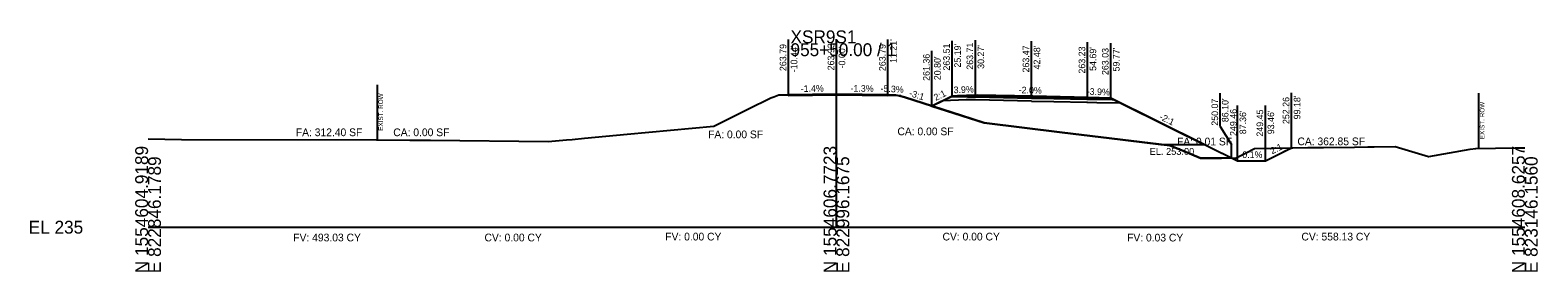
# Model space of a CAD drawing. Extents: x -26 to 823017, y -16 to 1558356.
# Drawn here: x -25.7 to 302.8, y 3490.3 to 3542.8 of the extents above; entities that cross this region are included whole.
import ezdxf

# ---------------------------------------------------------------- set-up
doc = ezdxf.new("R2010")
doc.units = 0
for name, color, linetype in [('ASPHALT_19MM1', 7, 'Continuous'), ('CONST_DCH', 7, 'Continuous'), ('CONST_LV3', 7, 'Continuous'), ('Draft_XS_Grid', 7, 'Continuous'), ('DTM_CORRIDOR', 7, 'Continuous'), ('DTM_P_FINISHED_GRADE2', 7, 'Continuous'), ('DTM_TEMP_DROP', 7, 'Continuous'), ('DTM_X_GROUND', 7, 'Continuous'), ('PROFILES_DCH_2', 7, 'Continuous'), ('XS_CELL', 7, 'Continuous'), ('XS_P_ASPHALT', 7, 'Continuous'), ('XS_P_DR_GRAVEL', 7, 'Continuous'), ('XS_P_GROUND', 7, 'Continuous'), ('XS_P_NULL_POINT', 7, 'Continuous'), ('XS_P_SHOULDER', 7, 'Continuous'), ('XS_P_SUBGRADE_GRANULAR', 7, 'Continuous'), ('XS_P_SUBGRADE_LEVELING', 7, 'Continuous'), ('XS_P_SUBGRADE_MILLING', 7, 'Continuous'), ('XS_P_SUBGRADE_UNDERCUT', 7, 'Continuous'), ('XS_P_TX_CLEARZONE', 7, 'Continuous'), ('XS_P_TX_FS_BS', 7, 'Continuous'), ('XS_SHEET_EW_TX_AREA', 7, 'Continuous'), ('XS_SHEET_EW_TX_VOLUME', 7, 'Continuous'), ('XS_X_ROW', 7, 'Continuous')]:
    doc.layers.add(name, color=color, linetype=linetype)

msp = doc.modelspace()

# ---------------------------------------------------------------- linework, layer by layer
at = {"layer": 'ASPHALT_19MM1'}
msp.add_lwpolyline([(180.27, 3528.34), (192.48, 3528.1), (197.4, 3528), (204.55, 3527.86), (204.69, 3527.86), (204.69, 3528.06), (204.55, 3528.07), (197.4, 3528.21), (192.48, 3528.31), (180.27, 3528.55), (180.27, 3528.34)], dxfattribs=at)
at = {"layer": 'CONST_DCH'}
msp.add_lwpolyline([(180.27, 3528.55), (192.48, 3528.31), (197.4, 3528.21), (204.55, 3528.07), (204.69, 3528.06), (204.69, 3528.23), (204.55, 3528.23), (197.4, 3528.37), (192.48, 3528.47), (180.27, 3528.71), (180.27, 3528.55)], dxfattribs=at)
at = {"layer": 'CONST_LV3'}
for points in [[(0, 3519.21), (7.25, 3519.1), (49.77, 3518.97), (57.04, 3518.94), (61.52, 3518.93), (87.16, 3518.66), (91.17, 3518.98), (92.43, 3519.1), (95.09, 3519.35), (104.41, 3520.21), (123.29, 3521.97), (130.66, 3525.65), (135.69, 3528.14), (136.35, 3528.38), (137.42, 3528.76), (139.56, 3528.79), (139.56, 3528.79)], [(150, 3528.93), (164, 3528.65)], [(161.21, 3528.79), (161.21, 3528.79), (162.9, 3528.77), (163.77, 3528.54), (164.84, 3528.27), (170.5, 3526.46), (170.8, 3526.36), (171, 3526.46), (175.19, 3528.51), (178.63, 3528.65), (180.27, 3528.71), (188.61, 3528.55), (192.48, 3528.47), (197.4, 3528.37), (200.08, 3528.32), (204.55, 3528.23), (204.69, 3528.23), (204.7, 3528.23), (209.77, 3528.03), (230.38, 3517.89), (237.36, 3514.46), (241.3, 3514.45), (243.46, 3514.45), (246.87, 3516.12), (247.8, 3516.58), (249.07, 3517.21), (249.18, 3517.26), (249.48, 3517.26), (252.74, 3517.32), (262.88, 3517.43), (265.76, 3517.47), (266.2, 3517.47), (266.78, 3517.48), (267.16, 3517.48), (271.74, 3517.52), (279.04, 3515.41), (279.1, 3515.39), (288.11, 3516.94), (289.31, 3517.13), (297.91, 3517.26), (300, 3517.29)], [(163.36, 3528.67), (164, 3528.65), (164, 3528.65)], [(170.8, 3526.36), (171, 3526.46), (175.19, 3528.51), (176.41, 3528.56), (180.27, 3528.71)], [(209.77, 3528.03), (224.38, 3520.84), (236.1, 3515.07)]]:
    msp.add_lwpolyline(points, dxfattribs=at)
at = {"layer": 'DTM_P_FINISHED_GRADE2'}
msp.add_lwpolyline([(139.56, 3528.79), (150, 3528.93), (161.21, 3528.79)], dxfattribs=at)
at = {"layer": 'DTM_X_GROUND'}
for points in [[(0, 3519.21), (7.25, 3519.1), (49.77, 3518.97), (57.04, 3518.94), (61.52, 3518.93), (87.16, 3518.66), (91.17, 3518.98), (92.43, 3519.1), (95.09, 3519.35), (104.41, 3520.21), (123.29, 3521.97), (130.66, 3525.65), (135.69, 3528.14), (136.35, 3528.38), (137.42, 3528.76), (146.92, 3528.89), (150.25, 3528.93), (153.12, 3528.89), (162.9, 3528.77), (163.77, 3528.54), (164.84, 3528.27), (177.24, 3524.29), (182.18, 3522.7), (199.2, 3520.63), (222.63, 3517.76), (225.55, 3516.58), (229.34, 3515.02), (233.93, 3515.05), (237.08, 3515.08), (239.28, 3516.15), (241.1, 3517.13), (249.48, 3517.28), (262.88, 3517.43), (266.78, 3517.48), (271.74, 3517.52), (279.04, 3515.41), (279.1, 3515.39), (288.11, 3516.94), (289.31, 3517.13), (297.91, 3517.26), (300, 3517.29)], [(0, 3519.21), (7.25, 3519.1), (49.77, 3518.97), (57.04, 3518.94), (61.52, 3518.93), (87.16, 3518.66), (91.17, 3518.98), (92.43, 3519.1), (95.09, 3519.35), (104.41, 3520.21), (123.29, 3521.97), (130.66, 3525.65), (135.69, 3528.14), (136.35, 3528.38), (137.42, 3528.76), (146.92, 3528.89), (150.25, 3528.93), (153.12, 3528.89), (162.9, 3528.77), (163.77, 3528.54), (164.84, 3528.27), (170.5, 3526.46), (170.8, 3526.36), (171, 3526.46), (175.19, 3528.51), (178.63, 3528.65), (180.27, 3528.71), (188.61, 3528.55), (192.48, 3528.47), (197.4, 3528.37), (200.08, 3528.32), (204.55, 3528.23), (204.69, 3528.23), (204.7, 3528.23), (209.77, 3528.03), (230.38, 3517.89), (237.36, 3514.46), (241.3, 3514.45), (243.46, 3514.45), (246.87, 3516.12), (247.8, 3516.58), (249.07, 3517.21), (249.18, 3517.26), (249.48, 3517.26), (252.74, 3517.32), (262.88, 3517.43), (265.76, 3517.47), (266.2, 3517.47), (266.78, 3517.48), (267.16, 3517.48), (271.74, 3517.52), (279.04, 3515.41), (279.1, 3515.39), (288.11, 3516.94), (289.31, 3517.13), (297.91, 3517.26), (300, 3517.29)], [(0, 3519.21), (7.25, 3519.1), (49.77, 3518.97), (57.04, 3518.94), (61.52, 3518.93), (87.16, 3518.66), (91.17, 3518.98), (92.43, 3519.1), (95.09, 3519.35), (104.41, 3520.21), (123.29, 3521.97), (130.66, 3525.65), (135.69, 3528.14), (136.35, 3528.38), (137.42, 3528.76), (139.56, 3528.79), (139.56, 3528.79), (150, 3528.93), (150, 3528.93), (150, 3528.93), (150, 3528.93), (150, 3528.93), (150, 3528.93), (150, 3528.93), (150, 3528.93), (161.21, 3528.79), (161.21, 3528.79), (161.21, 3528.79), (162.9, 3528.77), (163.77, 3528.54), (164.84, 3528.27), (170.5, 3526.46), (170.8, 3526.36), (171, 3526.46), (175.19, 3528.51), (178.63, 3528.65), (180.27, 3528.71), (188.61, 3528.55), (192.48, 3528.47), (197.4, 3528.37), (200.08, 3528.32), (204.55, 3528.23), (204.69, 3528.23), (204.7, 3528.23), (209.77, 3528.03), (230.38, 3517.89), (237.36, 3514.46), (241.3, 3514.45), (243.46, 3514.45), (246.87, 3516.12), (247.8, 3516.58), (249.07, 3517.21), (249.18, 3517.26), (249.48, 3517.26), (252.74, 3517.32), (262.88, 3517.43), (265.76, 3517.47), (266.2, 3517.47), (266.78, 3517.48), (267.16, 3517.48), (271.74, 3517.52), (279.04, 3515.41), (279.1, 3515.39), (288.11, 3516.94), (289.31, 3517.13), (297.91, 3517.26), (300, 3517.29)]]:
    msp.add_lwpolyline(points, dxfattribs=at)
at = {"layer": 'XS_CELL'}
for p, q in [((150, 3500), (150, 3540)), ((0, 3500), (150, 3500)), ((150, 3500), (300, 3500))]:
    msp.add_line(p, q, dxfattribs=at)
at = {"layer": 'XS_P_ASPHALT'}
msp.add_lwpolyline([(139.56, 3528.66), (150, 3528.8), (150, 3528.8), (161.21, 3528.66), (161.21, 3528.66), (161.21, 3528.79), (161.21, 3528.79), (150, 3528.93), (150, 3528.93), (139.56, 3528.79), (139.56, 3528.66)], dxfattribs=at)
at = {"layer": 'XS_P_DR_GRAVEL'}
for points in [[(176.41, 3528.56), (175.19, 3528.51), (175.07, 3528.46), (175.04, 3528.44), (178.59, 3528.37), (180.27, 3528.34), (180.27, 3528.48), (180.27, 3528.71), (176.41, 3528.56)], [(209.53, 3528.04), (204.69, 3528.23), (204.69, 3527.86), (204.69, 3527.86), (210.05, 3527.75), (210.36, 3527.74), (210.32, 3527.76), (209.77, 3528.03), (209.53, 3528.04)]]:
    msp.add_lwpolyline(points, dxfattribs=at)
at = {"layer": 'XS_P_GROUND'}
for points in [[(163.76, 3528.54), (163.36, 3528.67), (163.36, 3528.67)], [(236.1, 3515.07), (233.93, 3515.05), (233.93, 3515.05), (229.34, 3515.02), (229.34, 3515.02), (229.34, 3515.02), (225.55, 3516.58), (225.55, 3516.58), (222.63, 3517.76), (222.63, 3517.76), (199.2, 3520.63), (199.2, 3520.63), (182.18, 3522.7), (177.24, 3524.29), (177.24, 3524.29), (164.84, 3528.27), (164.84, 3528.27), (164.84, 3528.27), (163.77, 3528.54), (163.77, 3528.54), (163.77, 3528.54), (163.76, 3528.54)], [(163.76, 3528.54), (163.77, 3528.54), (163.77, 3528.54), (163.77, 3528.54), (164.84, 3528.27), (164.84, 3528.27), (164.84, 3528.27), (177.24, 3524.29), (177.24, 3524.29), (182.18, 3522.7), (199.2, 3520.63), (199.2, 3520.63), (222.63, 3517.76), (222.63, 3517.76), (225.55, 3516.58), (225.55, 3516.58), (229.34, 3515.02), (229.34, 3515.02), (229.34, 3515.02), (233.93, 3515.05), (233.93, 3515.05), (236.1, 3515.07)], [(175.19, 3528.51), (170.8, 3526.36)], [(209.77, 3528.03), (237.36, 3514.46), (243.46, 3514.45), (249.18, 3517.26)]]:
    msp.add_lwpolyline(points, dxfattribs=at)
at = {"layer": 'XS_P_SHOULDER'}
for points in [[(175.19, 3528.51), (176.41, 3528.56), (180.27, 3528.71)], [(209.77, 3528.03), (209.53, 3528.04), (204.69, 3528.23)]]:
    msp.add_lwpolyline(points, dxfattribs=at)
at = {"layer": 'XS_P_SUBGRADE_GRANULAR'}
for points in [[(180.27, 3527.67), (178.24, 3527.71), (173.15, 3527.51)], [(192.48, 3527.43), (180.27, 3527.67)], [(192.48, 3527.43), (197.4, 3527.33), (204.55, 3527.19), (204.69, 3527.19)], [(204.69, 3527.19), (206.72, 3527.15), (211.77, 3527.05)]]:
    msp.add_lwpolyline(points, dxfattribs=at)
at = {"layer": 'XS_P_SUBGRADE_LEVELING'}
msp.add_lwpolyline([(139.56, 3528.66), (146.92, 3528.76), (146.92, 3528.76), (150, 3528.8), (150.25, 3528.8), (150.25, 3528.8), (153.12, 3528.77), (153.12, 3528.77), (161.21, 3528.66), (161.21, 3528.66)], dxfattribs=at)
msp.add_lwpolyline([(139.56, 3528.66), (146.92, 3528.76), (146.92, 3528.76), (150, 3528.8), (150.25, 3528.8), (150.25, 3528.8), (153.12, 3528.77), (153.12, 3528.77), (161.21, 3528.66), (161.21, 3528.66)], dxfattribs=at)
at = {"layer": 'XS_P_SUBGRADE_MILLING'}
msp.add_lwpolyline([(161.21, 3528.79), (161.21, 3528.79), (161.21, 3528.66), (161.21, 3528.66), (153.12, 3528.77), (153.12, 3528.77), (150.25, 3528.8), (150.25, 3528.8), (150, 3528.8), (146.92, 3528.76), (146.92, 3528.76), (139.56, 3528.66), (139.56, 3528.79), (146.92, 3528.89), (146.92, 3528.89), (150, 3528.93), (150.25, 3528.93), (150.25, 3528.93), (153.12, 3528.89), (153.12, 3528.89), (161.21, 3528.79)], dxfattribs=at)
at = {"layer": 'XS_P_SUBGRADE_UNDERCUT'}
msp.add_lwpolyline([(170.8, 3526.36), (182.18, 3522.7), (220.68, 3518), (230.16, 3518), (209.77, 3528.03), (204.77, 3528.23), (192.77, 3528.47), (180.77, 3528.71), (175.19, 3528.51)], close=True, dxfattribs=at)
at = {"layer": 'XS_P_TX_CLEARZONE'}
for p, q in [((139.56, 3528.79), (139.56, 3540.79)), ((150, 3528.93), (150, 3540.93)), ((161.21, 3528.79), (161.21, 3540.79)), ((170.8, 3526.36), (170.8, 3538.36)), ((175.19, 3528.51), (175.19, 3540.51)), ((180.27, 3528.71), (180.27, 3540.71)), ((192.48, 3528.47), (192.48, 3540.47)), ((204.69, 3528.23), (204.69, 3540.23)), ((209.77, 3528.03), (209.77, 3540.03)), ((233.61, 3521.9), (233.61, 3529.15)), ((249.18, 3517.26), (249.18, 3529.26)), ((237.36, 3514.46), (237.36, 3526.46)), ((243.46, 3514.45), (243.46, 3526.45)), ((233.61, 3521.9), (236.1, 3518.01)), ((236.1, 3515.07), (236.1, 3518.01))]:
    msp.add_line(p, q, dxfattribs=at)
at = {"layer": 'XS_X_ROW'}
for p, q in [((50, 3518.97), (50, 3530.97)), ((290, 3517.14), (290, 3529.14))]:
    msp.add_line(p, q, dxfattribs=at)

# ---------------------------------------------------------------- texts
at = {"layer": 'CONST_DCH'}
for p in [(170.72, 3526.24), (236.03, 3514.95), (237.28, 3514.34)]:
    msp.add_text('X', height=0.24, dxfattribs=at).set_placement(p)
at = {"layer": 'Draft_XS_Grid'}
msp.add_text('-', height=0.0001, dxfattribs=at).set_placement((0, 3500))
at = {"layer": 'DTM_CORRIDOR'}
for p in [(180.19, 3528.59), (192.41, 3528.35), (204.61, 3528.11)]:
    msp.add_text('X', height=0.24, dxfattribs=at).set_placement(p)
at = {"layer": 'DTM_TEMP_DROP'}
for p in [(139.48, 3528.67), (149.92, 3528.81), (161.13, 3528.67)]:
    msp.add_text('X', height=0.24, dxfattribs=at).set_placement(p)
at = {"layer": 'PROFILES_DCH_2'}
for p in [(163.28, 3528.55), (163.68, 3528.42), (236.03, 3514.95)]:
    msp.add_text('X', height=0.24, dxfattribs=at).set_placement(p)
at = {"layer": 'XS_CELL'}
for s, p in [('XSR9S1', (140, 3540)), ('955+50.00 / 1', (140, 3537.2)), ('EL 235', (-26, 3498.6))]:
    msp.add_text(s, height=2.8, dxfattribs=at).set_placement(p)
for s, p in [('N 1554604.9189', (0, 3490)), ('N 1554606.7723', (150, 3490)), ('N 1554608.6257', (300, 3490)), ('E 822846.1789', (2.8, 3490)), ('E 822996.1675', (152.8, 3490)), ('E 823146.1560', (302.8, 3490))]:
    msp.add_text(s, height=2.8, rotation=90, dxfattribs=at).set_placement(p)
at = {"layer": 'XS_P_ASPHALT'}
for p in [(170.72, 3526.24), (249.1, 3517.14)]:
    msp.add_text('X', height=0.24, dxfattribs=at).set_placement(p)
at = {"layer": 'XS_P_NULL_POINT'}
msp.add_text('X', height=0.24, dxfattribs=at).set_placement((243.38, 3514.33))
at = {"layer": 'XS_P_SHOULDER'}
for p in [(175.11, 3528.39), (209.7, 3527.91)]:
    msp.add_text('X', height=0.24, dxfattribs=at).set_placement(p)
at = {"layer": 'XS_P_SUBGRADE_UNDERCUT'}
msp.add_text('EL. 253.00', height=1.5, dxfattribs=at).set_placement((218.26, 3515.73))
at = {"layer": 'XS_P_TX_CLEARZONE'}
for s, p in [('263.79', (139.08, 3533.95)), ("-10.44'", (141.48, 3533.69)), ('263.93', (149.52, 3534.11)), ("-0.00'", (151.92, 3534.54)), ('263.79', (160.73, 3533.95)), ("11.21'", (163.13, 3535.71)), ('263.51', (174.71, 3534.05)), ("25.19'", (177.11, 3534.71)), ('263.71', (179.79, 3534.25)), ("30.27'", (182.19, 3534.44)), ('263.47', (192, 3533.65)), ("42.48'", (194.4, 3534.31)), ('263.23', (204.21, 3533.41)), ("54.69'", (206.61, 3534)), ('263.03', (209.29, 3533.09)), ("59.77'", (211.69, 3533.87)), ('261.36', (170.32, 3531.82)), ("20.80'", (172.72, 3531.97)), ("99.18'", (251.1, 3523.46)), ('250.07', (233.17, 3522.07)), ("86.10'", (235.43, 3522.84)), ('249.46', (237.21, 3519.84)), ("87.36'", (239.28, 3520.22)), ('249.45', (242.98, 3519.7)), ("93.46'", (245.38, 3520.22)), ('252.26', (248.7, 3522.43))]:
    msp.add_text(s, height=1.44, rotation=90, dxfattribs=at).set_placement(p)
at = {"layer": 'XS_P_TX_FS_BS'}
for s, rotation, p in [('-1.4%', 0.783, (142.22, 3529.42)), ('-1.3%', 359.2829, (153.06, 3529.49)), ('-5.3%', 356.9619, (159.59, 3529.48)), ('-3:1', 342.7739, (165.72, 3528.56)), ('2:1', 26.1625, (171.63, 3527.44)), ('3.9%', 2.2445, (175.56, 3529.13)), ('-2.0%', 358.8674, (189.7, 3529.13)), ('-3.9%', 357.7397, (204.52, 3528.84)), ('-2:1', 333.7979, (220.23, 3523.54)), ('-0.1%', 359.9678, (237.8, 3515.05)), ('2:1', 26.1504, (244.96, 3515.85))]:
    msp.add_text(s, height=1.44, rotation=rotation, dxfattribs=at).set_placement(p)
at = {"layer": 'XS_SHEET_EW_TX_AREA'}
for s, p in [('FA: 312.40 SF', (32.2, 3519.8)), ('CA: 0.00 SF', (53.43, 3519.8)), ('FA: 0.00 SF', (122.03, 3519.35)), ('CA: 0.00 SF', (163.29, 3520)), ('FA: 0.01 SF', (224.22, 3517.79)), ('CA: 362.85 SF', (250.45, 3517.83))]:
    msp.add_text(s, height=1.68, dxfattribs=at).set_placement(p)
at = {"layer": 'XS_SHEET_EW_TX_VOLUME'}
for s, p in [('FV: 493.03 CY', (31.64, 3496.92)), ('CV: 0.00 CY', (73.31, 3496.92)), ('FV: 0.00 CY', (112.7, 3497.12)), ('CV: 0.00 CY', (173.12, 3497.12)), ('FV: 0.03 CY', (213.33, 3496.9)), ('CV: 558.13 CY', (251.33, 3497.12))]:
    msp.add_text(s, height=1.68, dxfattribs=at).set_placement(p)
at = {"layer": 'XS_X_ROW'}
for p in [(51.2, 3520.97), (291.2, 3519.14)]:
    msp.add_text('EXIST. ROW', height=1, rotation=90, dxfattribs=at).set_placement(p)

doc.saveas('drawing.dxf')
